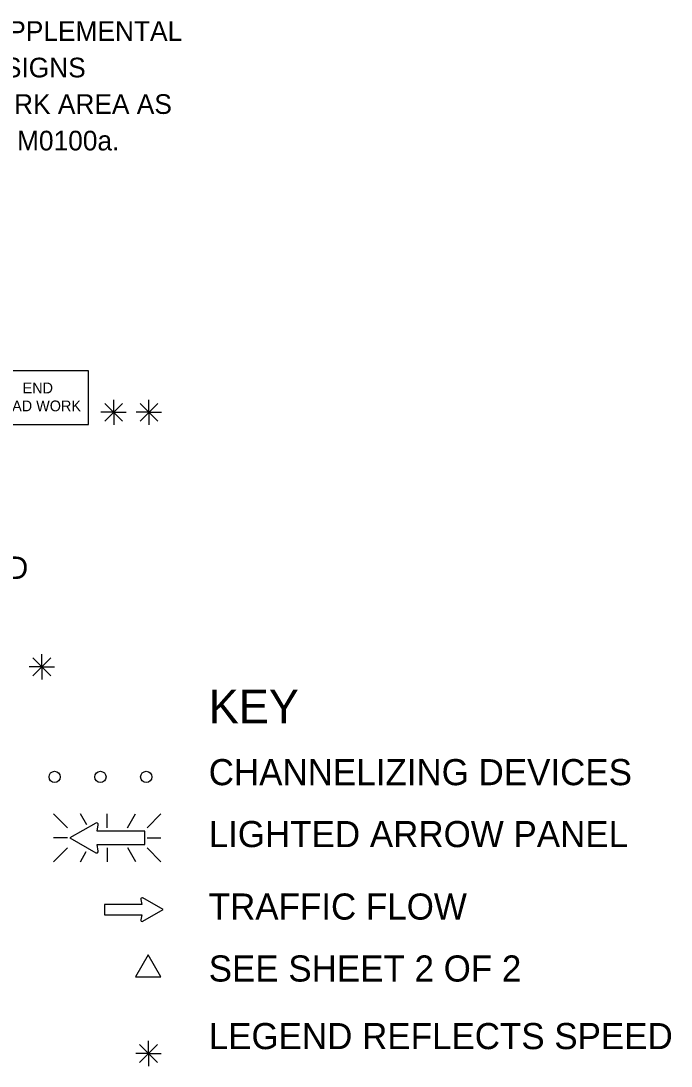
# Model space of a CAD drawing. Extents: x 16731 to 18464, y 5737 to 6974.
# Drawn here: x 17187.1 to 17418.5, y 6535.4 to 6907.5 of the extents above; entities that cross this region are included whole.
import ezdxf

# ---------------------------------------------------------------- set-up
doc = ezdxf.new("R2010")
doc.units = 0
for name, color, linetype in [('MT_SCRATCH_LEVEL_E', 7, 'Continuous'), ('TRAFFIC_SIGNS_PR', 7, 'Continuous'), ('TYPICAL_TEXT_DIMEN_EX', 7, 'Continuous'), ('TYPICAL_TEXT_DIMEN_PR', 7, 'Continuous')]:
    doc.layers.add(name, color=color, linetype=linetype)

msp = doc.modelspace()

# ---------------------------------------------------------------- linework, layer by layer
at = {"layer": 'MT_SCRATCH_LEVEL_E'}
for p, q in [((17230.09, 6593.02), (17216.83, 6593.02)), ((17216.83, 6593.02), (17216.83, 6589.28)), ((17229.77, 6594.8), (17230.09, 6593.02)), ((17237.7, 6591.17), (17230.46, 6595.28)), ((17216.83, 6589.28), (17230.09, 6589.28)), ((17230.09, 6589.28), (17229.77, 6587.5)), ((17230.46, 6587.02), (17237.7, 6591.17))]:
    msp.add_line(p, q, dxfattribs=at)
for centre, start, end in [((17230.23, 6594.87), 60.4248, 189.9638), ((17230.23, 6587.43), 170.0362, 299.7731)]:
    msp.add_arc(centre, 0.463, start, end, dxfattribs=at)
at = {"layer": 'TRAFFIC_SIGNS_PR'}
for p, q in [((17198.76, 6625.18), (17203.7, 6620.24)), ((17210.53, 6621.35), (17208.32, 6625.18)), ((17217.85, 6620.24), (17217.85, 6625.18)), ((17225.08, 6620.24), (17227.93, 6625.18)), ((17232, 6620.24), (17236.93, 6625.18)), ((17203.7, 6616.69), (17198.76, 6616.69)), ((17232, 6616.69), (17236.93, 6616.69)), ((17198.76, 6608.2), (17203.7, 6613.13)), ((17208.28, 6608.2), (17210.39, 6611.86)), ((17217.85, 6613.13), (17217.85, 6608.2)), ((17227.98, 6608.2), (17225.13, 6613.13)), ((17232, 6613.13), (17236.93, 6608.19))]:
    msp.add_line(p, q, dxfattribs=at)
msp.add_lwpolyline([(17172.71, 6763.79), (17211.11, 6763.79), (17211.11, 6782.99), (17172.71, 6782.99)], close=True, dxfattribs=at)
for points in [[(17213.77, 6621.96), (17204.48, 6616.69), (17213.78, 6611.37)], [(17214.65, 6611.99), (17214.25, 6614.26), (17231.26, 6614.26), (17231.26, 6619.06), (17214.25, 6619.06), (17214.65, 6621.34)]]:
    msp.add_lwpolyline(points, dxfattribs=at)
for centre in [(17199.11, 6638.37), (17215.41, 6638.37), (17231.71, 6638.37)]:
    msp.add_circle(centre, 2, dxfattribs=at)
for centre, radius, start, end in [((17214.06, 6621.44), 0.598, 350.7308, 118.8916), ((17214.06, 6611.89), 0.597, 241.4833, 9.9593)]:
    msp.add_arc(centre, radius, start, end, dxfattribs=at)
at = {"layer": 'TYPICAL_TEXT_DIMEN_PR'}
for p, q in [((17220.14, 6768.16), (17220.14, 6772.62)), ((17232.69, 6768.16), (17232.69, 6772.62)), ((17220.14, 6768.16), (17215.6, 6768.16)), ((17216.95, 6771.35), (17223.32, 6764.98)), ((17223.32, 6771.35), (17216.95, 6764.98)), ((17220.14, 6768.16), (17223.32, 6768.16)), ((17220.14, 6768.16), (17224.61, 6768.16)), ((17220.14, 6768.16), (17220.14, 6763.66)), ((17232.69, 6768.16), (17228.16, 6768.16)), ((17235.88, 6771.35), (17229.5, 6764.98)), ((17229.51, 6771.35), (17235.88, 6764.98)), ((17232.69, 6768.16), (17235.88, 6768.16)), ((17232.69, 6768.16), (17237.17, 6768.16)), ((17232.69, 6768.16), (17232.69, 6763.66)), ((17191.35, 6680.76), (17197.72, 6674.38)), ((17197.72, 6680.76), (17191.35, 6674.38)), ((17194.54, 6677.57), (17194.54, 6682.03)), ((17194.54, 6677.57), (17190.01, 6677.57)), ((17194.54, 6677.57), (17197.72, 6677.57)), ((17194.54, 6677.57), (17199.01, 6677.57)), ((17194.54, 6677.57), (17194.54, 6673.07)), ((17229.31, 6543.12), (17235.68, 6536.75)), ((17235.68, 6543.12), (17229.31, 6536.75)), ((17232.5, 6539.94), (17232.5, 6544.39)), ((17232.5, 6539.94), (17227.96, 6539.94)), ((17232.5, 6539.94), (17235.68, 6539.94)), ((17232.5, 6539.94), (17236.97, 6539.94)), ((17232.5, 6539.94), (17232.5, 6535.44))]:
    msp.add_line(p, q, dxfattribs=at)
msp.add_lwpolyline([(17232.41, 6575), (17227.89, 6567.16), (17236.94, 6567.16)], close=True, dxfattribs=at)

# ---------------------------------------------------------------- texts
at = {"layer": 'TRAFFIC_SIGNS_PR'}
for s, height, p in [('PLACE ADDITIONAL SUPPLEMENTAL', 7, (17077.54, 6900.39)), ('SETS OF SPEED LIMIT SIGNS', 7, (17077.54, 6887.39)), ('THROUGHOUT THE WORK AREA AS', 7, (17077.54, 6874.39)), ('DEPICTED ON TYPICAL M0100a.', 7, (17077.54, 6861.39)), ('END', 3.831, (17187.71, 6774.92)), ('ROAD WORK', 3.831, (17176.32, 6768.53)), ('SPEED', 8, (17153.45, 6708.85))]:
    msp.add_text(s, height=height, dxfattribs=at).set_placement(p)
at = {"layer": 'TYPICAL_TEXT_DIMEN_EX'}
for s, height, p in [('KEY', 12, (17253.95, 6657.48)), ('CHANNELIZING DEVICES', 9.3, (17253.95, 6635.43)), ('LIGHTED ARROW PANEL', 9.3, (17253.95, 6613.38)), ('TRAFFIC FLOW', 9.3, (17253.95, 6587.58)), ('SEE SHEET 2 OF 2', 9.3, (17253.95, 6565.53)), ('LEGEND REFLECTS SPEED', 9.3, (17253.95, 6541.47))]:
    msp.add_text(s, height=height, dxfattribs=at).set_placement(p)

doc.saveas('drawing.dxf')
